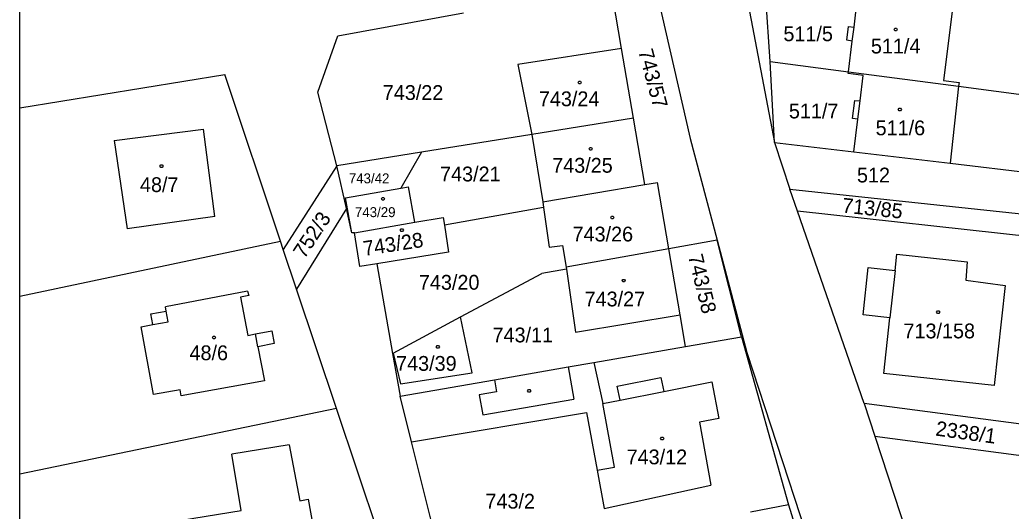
# Model space of a CAD drawing. Extents: x -639590 to -639298, y -1193269 to -1192863.
# Drawn here: x -639590.4 to -639476.5, y -1193051.8 to -1192995.4 of the extents above; entities that cross this region are included whole.
import ezdxf

# ---------------------------------------------------------------- set-up
doc = ezdxf.new("R2010")
doc.units = 0
for name, color, linetype in [('Vrstva 1', 7, 'Continuous'), ('Vrstva 2', 7, 'Continuous'), ('Vrstva 4', 7, 'Continuous'), ('Vrstva 5', 7, 'Continuous'), ('Vrstva 61', 7, 'Continuous')]:
    doc.layers.add(name, color=color, linetype=linetype)

msp = doc.modelspace()

# ---------------------------------------------------------------- linework, layer by layer
at = {"layer": 'Vrstva 1'}
for p, q in [((-639518.33, -1192987.4), (-639513.38, -1193008.98)), ((-639507.5, -1192989.45), (-639503.7, -1193009.43)), ((-639521.26, -1192998.64), (-639522.49, -1192991.48)), ((-639504.21, -1193000.14), (-639504.82, -1192990.96)), ((-639494.57, -1192996.2), (-639494.14, -1192992.64)), ((-639483.21, -1192993.78), (-639484.31, -1193002.34)), ((-639553.86, -1192997.18), (-639539.42, -1192994.56)), ((-639495.4, -1192997.71), (-639495.21, -1192996.13)), ((-639495.21, -1192996.13), (-639494.57, -1192996.2)), ((-639556.15, -1193003.67), (-639553.86, -1192997.18)), ((-639494.77, -1192997.79), (-639495.4, -1192997.71)), ((-639495.21, -1193001.32), (-639494.77, -1192997.79)), ((-639521.26, -1192998.64), (-639533.19, -1193000.49)), ((-639519.89, -1193006.67), (-639521.26, -1192998.64)), ((-639533.19, -1193000.49), (-639531.56, -1193008.54)), ((-639503.7, -1193009.43), (-639504.21, -1193000.14)), ((-639504.21, -1193000.14), (-639495.21, -1193001.32)), ((-639590.39, -1193005.46), (-639566.86, -1193001.65)), ((-639560.45, -1193020.79), (-639566.86, -1193001.65)), ((-639495.23, -1193001.51), (-639495.21, -1193001.32)), ((-639493.52, -1193001.76), (-639495.23, -1193001.51)), ((-639495.21, -1193001.32), (-639482.56, -1193002.99)), ((-639493.88, -1193004.68), (-639493.52, -1193001.76)), ((-639484.31, -1193002.34), (-639482.51, -1193002.57)), ((-639482.56, -1193002.99), (-639483.54, -1193011.82)), ((-639482.51, -1193002.57), (-639482.56, -1193002.99)), ((-639482.56, -1193002.99), (-639459.99, -1193005.96)), ((-639553.99, -1193012.12), (-639556.15, -1193003.67)), ((-639494.73, -1193006.69), (-639494.47, -1193004.61)), ((-639494.47, -1193004.61), (-639493.88, -1193004.68)), ((-639519.89, -1193006.67), (-639531.56, -1193008.54)), ((-639518.6, -1193014.29), (-639519.89, -1193006.67)), ((-639494.13, -1193006.76), (-639494.73, -1193006.69)), ((-639494.58, -1193010.51), (-639494.13, -1193006.76)), ((-639579.55, -1193009.22), (-639569.3, -1193007.9)), ((-639568, -1193017.94), (-639569.3, -1193007.9)), ((-639531.56, -1193008.54), (-639544.27, -1193010.57)), ((-639531.56, -1193008.54), (-639530.31, -1193016.28)), ((-639579.55, -1193009.22), (-639578.08, -1193019.37)), ((-639513.38, -1193008.98), (-639510.28, -1193020.67)), ((-639503.7, -1193009.43), (-639501.94, -1193014.81)), ((-639503.7, -1193009.43), (-639494.58, -1193010.51)), ((-639544.27, -1193010.57), (-639553.99, -1193012.12)), ((-639544.27, -1193010.57), (-639546.64, -1193014.7)), ((-639494.58, -1193010.51), (-639483.54, -1193011.82)), ((-639553.99, -1193012.12), (-639560.14, -1193021.73)), ((-639552.87, -1193017.05), (-639553.99, -1193012.12)), ((-639483.54, -1193011.82), (-639459.46, -1193014.67)), ((-639530.31, -1193016.28), (-639518.6, -1193014.29)), ((-639518.6, -1193014.29), (-639517.16, -1193014.04)), ((-639515.83, -1193021.66), (-639517.16, -1193014.04)), ((-639552.97, -1193015.81), (-639546.64, -1193014.7)), ((-639546.64, -1193014.7), (-639545.76, -1193014.55)), ((-639545.02, -1193018.62), (-639545.76, -1193014.55)), ((-639501.94, -1193014.81), (-639408.9, -1193024.71)), ((-639501.06, -1193017.35), (-639501.94, -1193014.81)), ((-639552.24, -1193019.83), (-639552.97, -1193015.81)), ((-639530.31, -1193016.28), (-639530.22, -1193016.93)), ((-639552.87, -1193017.05), (-639558.61, -1193026.29)), ((-639552.24, -1193019.83), (-639552.87, -1193017.05)), ((-639530.22, -1193016.93), (-639541.62, -1193018.94)), ((-639530.22, -1193016.93), (-639529.57, -1193021.47)), ((-639493.42, -1193039.43), (-639501.06, -1193017.35)), ((-639465.69, -1193021.25), (-639501.06, -1193017.35)), ((-639568, -1193017.94), (-639578.08, -1193019.37)), ((-639551.96, -1193019.82), (-639545.02, -1193018.62)), ((-639545.02, -1193018.62), (-639541.75, -1193018.05)), ((-639541.75, -1193018.05), (-639541.62, -1193018.94)), ((-639541.62, -1193018.94), (-639541.16, -1193022.03)), ((-639551.96, -1193019.82), (-639552.24, -1193019.83)), ((-639551.34, -1193023.7), (-639551.96, -1193019.82)), ((-639590.39, -1193027.1), (-639560.45, -1193020.79)), ((-639560.14, -1193021.73), (-639560.45, -1193020.79)), ((-639529.57, -1193021.47), (-639528.05, -1193021.28)), ((-639528.05, -1193021.28), (-639527.62, -1193023.76)), ((-639510.28, -1193020.67), (-639515.83, -1193021.66)), ((-639507.5, -1193031.78), (-639510.28, -1193020.67)), ((-639510.28, -1193020.67), (-639506.87, -1193033.57)), ((-639558.61, -1193026.29), (-639560.14, -1193021.73)), ((-639541.16, -1193022.03), (-639549.38, -1193023.38)), ((-639515.83, -1193021.66), (-639527.62, -1193023.76)), ((-639514.54, -1193029.25), (-639515.83, -1193021.66)), ((-639489.86, -1193024.14), (-639489.66, -1193022.27)), ((-639489.66, -1193022.27), (-639481.57, -1193023.17)), ((-639549.38, -1193023.38), (-639551.34, -1193023.7)), ((-639549.38, -1193023.38), (-639547.58, -1193033.68)), ((-639481.57, -1193023.17), (-639481.74, -1193025.25)), ((-639539.76, -1193029.49), (-639530.44, -1193024.49)), ((-639527.59, -1193024.01), (-639530.44, -1193024.49)), ((-639527.62, -1193023.76), (-639527.59, -1193024.01)), ((-639527.59, -1193024.01), (-639526.56, -1193031.23)), ((-639493.53, -1193029.25), (-639492.95, -1193023.81)), ((-639492.95, -1193023.81), (-639489.86, -1193024.14)), ((-639481.74, -1193025.25), (-639477.2, -1193025.86)), ((-639564.24, -1193026.51), (-639573.66, -1193028.32)), ((-639564.24, -1193026.51), (-639564.09, -1193027.02)), ((-639554.02, -1193040.01), (-639558.61, -1193026.29)), ((-639477.2, -1193025.86), (-639478.47, -1193037.37)), ((-639564.09, -1193027.02), (-639565.06, -1193027.2)), ((-639565.06, -1193027.2), (-639564.21, -1193031.61)), ((-639575.35, -1193029.14), (-639573.57, -1193028.81)), ((-639575.13, -1193030.37), (-639575.35, -1193029.14)), ((-639573.57, -1193028.81), (-639573.66, -1193028.32)), ((-639526.56, -1193031.23), (-639514.54, -1193029.25)), ((-639513.92, -1193032.9), (-639514.54, -1193029.25)), ((-639490.45, -1193029.58), (-639493.53, -1193029.25)), ((-639576.45, -1193030.61), (-639575.13, -1193030.37)), ((-639547.5, -1193033.64), (-639539.76, -1193029.49)), ((-639538.45, -1193035.9), (-639539.76, -1193029.49)), ((-639491.13, -1193035.97), (-639490.45, -1193029.58)), ((-639575.05, -1193038.4), (-639576.45, -1193030.61)), ((-639564.21, -1193031.61), (-639563.32, -1193031.44)), ((-639563.32, -1193031.44), (-639561.44, -1193031.08)), ((-639561.44, -1193031.08), (-639561.16, -1193032.56)), ((-639561.16, -1193032.56), (-639563.04, -1193032.92)), ((-639513.92, -1193032.9), (-639507.5, -1193031.78)), ((-639507.5, -1193031.78), (-639502.09, -1193051.09)), ((-639563.04, -1193032.92), (-639562.28, -1193036.82)), ((-639547.58, -1193033.68), (-639547.5, -1193033.64)), ((-639547.58, -1193033.68), (-639546.72, -1193038.6)), ((-639547.5, -1193033.64), (-639546.65, -1193037.16)), ((-639524.47, -1193034.73), (-639513.92, -1193032.9)), ((-639506.87, -1193033.57), (-639486.01, -1193097.33)), ((-639527.4, -1193035.24), (-639524.47, -1193034.73)), ((-639524.47, -1193034.73), (-639523.42, -1193039.45)), ((-639546.65, -1193037.16), (-639538.45, -1193035.9)), ((-639535.86, -1193036.71), (-639527.4, -1193035.24)), ((-639478.47, -1193037.37), (-639491.13, -1193035.97)), ((-639562.28, -1193036.82), (-639571.85, -1193038.54)), ((-639546.72, -1193038.6), (-639535.86, -1193036.71)), ((-639521.77, -1193037.44), (-639516.75, -1193036.43)), ((-639516.75, -1193036.43), (-639516.42, -1193038.04)), ((-639516.42, -1193038.04), (-639510.92, -1193036.93)), ((-639510.92, -1193036.93), (-639510.1, -1193041.14)), ((-639571.98, -1193037.85), (-639575.05, -1193038.4)), ((-639571.85, -1193038.54), (-639571.98, -1193037.85)), ((-639521.44, -1193039.05), (-639521.77, -1193037.44)), ((-639545.4, -1193043.83), (-639546.72, -1193038.6)), ((-639523.42, -1193039.45), (-639521.44, -1193039.05)), ((-639468.21, -1193042.77), (-639493.42, -1193039.43)), ((-639493.42, -1193039.43), (-639492.18, -1193043.2)), ((-639554.02, -1193040.01), (-639590.39, -1193047.55)), ((-639547.47, -1193059.58), (-639554.02, -1193040.01)), ((-639545.4, -1193043.83), (-639525.28, -1193040.46)), ((-639525.28, -1193040.46), (-639524.07, -1193047.11)), ((-639510.1, -1193041.14), (-639512.32, -1193041.56)), ((-639512.32, -1193041.56), (-639511.02, -1193048.83)), ((-639541.72, -1193058.45), (-639545.4, -1193043.83)), ((-639492.18, -1193043.2), (-639468.63, -1193046.32)), ((-639492.18, -1193043.2), (-639479.86, -1193080.55)), ((-639559.45, -1193044.19), (-639566.02, -1193045.25)), ((-639559.45, -1193044.19), (-639558.24, -1193050.62)), ((-639564.97, -1193051.71), (-639566.02, -1193045.25)), ((-639524.07, -1193047.11), (-639523.28, -1193051.49)), ((-639523.28, -1193051.49), (-639511.02, -1193048.83)), ((-639558.24, -1193050.62), (-639557.26, -1193050.41)), ((-639557.26, -1193050.41), (-639556.66, -1193053.85)), ((-639571.83, -1193052.82), (-639564.97, -1193051.71)), ((-639502.09, -1193051.09), (-639506.48, -1193051.9)), ((-639502.09, -1193051.09), (-639495.98, -1193070.66))]:
    msp.add_line(p, q, dxfattribs=at)
at = {"layer": 'Vrstva 4'}
for p, q in [((-639494.77, -1192997.79), (-639494.57, -1192996.2)), ((-639494.13, -1193006.76), (-639493.88, -1193004.68)), ((-639489.86, -1193024.14), (-639490.45, -1193029.58)), ((-639573.35, -1193030.05), (-639573.57, -1193028.81)), ((-639575.13, -1193030.37), (-639573.35, -1193030.05)), ((-639563.04, -1193032.92), (-639563.32, -1193031.44)), ((-639527.4, -1193035.24), (-639526.76, -1193038.93)), ((-639535.86, -1193036.71), (-639535.62, -1193038.09)), ((-639535.62, -1193038.09), (-639537.62, -1193038.44)), ((-639521.44, -1193039.05), (-639516.42, -1193038.04)), ((-639537.62, -1193038.44), (-639537.22, -1193040.75)), ((-639537.22, -1193040.75), (-639526.76, -1193038.93)), ((-639522.1, -1193046.75), (-639523.42, -1193039.45)), ((-639524.07, -1193047.11), (-639522.1, -1193046.75))]:
    msp.add_line(p, q, dxfattribs=at)
at = {"layer": 'Vrstva 5'}
for points in [[(-639489.69, -1192996.32), (-639489.6, -1192996.47), (-639489.69, -1192996.62), (-639489.87, -1192996.62), (-639489.96, -1192996.47), (-639489.87, -1192996.32)], [(-639526, -1193002.41), (-639525.91, -1193002.56), (-639526, -1193002.71), (-639526.18, -1193002.71), (-639526.27, -1193002.56), (-639526.18, -1193002.41)], [(-639489.22, -1193005.52), (-639489.13, -1193005.67), (-639489.22, -1193005.82), (-639489.4, -1193005.82), (-639489.49, -1193005.67), (-639489.4, -1193005.52)], [(-639524.73, -1193010.04), (-639524.64, -1193010.19), (-639524.73, -1193010.34), (-639524.91, -1193010.34), (-639525, -1193010.19), (-639524.91, -1193010.04)], [(-639574.03, -1193012.01), (-639573.94, -1193012.16), (-639574.03, -1193012.31), (-639574.21, -1193012.31), (-639574.3, -1193012.16), (-639574.21, -1193012.01)], [(-639548.59, -1193015.77), (-639548.5, -1193015.92), (-639548.59, -1193016.07), (-639548.77, -1193016.07), (-639548.86, -1193015.92), (-639548.77, -1193015.77)], [(-639522.25, -1193017.92), (-639522.16, -1193018.07), (-639522.25, -1193018.22), (-639522.43, -1193018.22), (-639522.52, -1193018.07), (-639522.43, -1193017.92)], [(-639546.42, -1193019.38), (-639546.33, -1193019.53), (-639546.42, -1193019.68), (-639546.6, -1193019.68), (-639546.69, -1193019.53), (-639546.6, -1193019.38)], [(-639520.94, -1193025.17), (-639520.85, -1193025.32), (-639520.94, -1193025.47), (-639521.12, -1193025.47), (-639521.21, -1193025.32), (-639521.12, -1193025.17)], [(-639484.81, -1193028.78), (-639484.72, -1193028.93), (-639484.81, -1193029.08), (-639484.99, -1193029.08), (-639485.08, -1193028.93), (-639484.99, -1193028.78)], [(-639568, -1193031.7), (-639567.91, -1193031.85), (-639568, -1193032), (-639568.18, -1193032), (-639568.27, -1193031.85), (-639568.18, -1193031.7)], [(-639542.29, -1193032.79), (-639542.2, -1193032.94), (-639542.29, -1193033.09), (-639542.47, -1193033.09), (-639542.56, -1193032.94), (-639542.47, -1193032.79)], [(-639531.8, -1193037.83), (-639531.71, -1193037.98), (-639531.8, -1193038.13), (-639531.98, -1193038.13), (-639532.07, -1193037.98), (-639531.98, -1193037.83)], [(-639516.51, -1193043.29), (-639516.42, -1193043.44), (-639516.51, -1193043.59), (-639516.69, -1193043.59), (-639516.78, -1193043.44), (-639516.69, -1193043.29)]]:
    msp.add_lwpolyline(points, close=True, dxfattribs=at)
at = {"layer": 'Vrstva 61'}
msp.add_lwpolyline([(-639590.39, -1193268.77), (-639590.39, -1192863.27)], dxfattribs=at)

# ---------------------------------------------------------------- texts
at = {"layer": 'Vrstva 2'}
for s, height, p in [('511/5', 1.7, (-639502.68, -1192997.81)), ('511/4', 1.7, (-639492.63, -1192999.22)), ('743/22', 1.7, (-639548.7, -1193004.56)), ('743/24', 1.7, (-639530.77, -1193005.28)), ('511/7', 1.7, (-639502.05, -1193006.68)), ('511/6', 1.7, (-639492.09, -1193008.62)), ('743/21', 1.7, (-639542.12, -1193013.92)), ('743/25', 1.7, (-639529.24, -1193012.92)), ('743/42', 1.14, (-639552.6, -1193014.14)), ('512', 1.7, (-639494.23, -1193014.04)), ('48/7', 1.7, (-639576.59, -1193015.14)), ('743/29', 1.14, (-639551.9, -1193018.02)), ('743/26', 1.7, (-639526.9, -1193020.82)), ('743/20', 1.7, (-639544.55, -1193026.36)), ('743/27', 1.7, (-639525.52, -1193028.28)), ('713/158', 1.7, (-639488.89, -1193031.95)), ('743/11', 1.7, (-639536.09, -1193032.41)), ('48/6', 1.7, (-639570.9, -1193034.46)), ('743/39', 1.7, (-639547.17, -1193035.68)), ('743/12', 1.7, (-639520.69, -1193046.42)), ('743/2', 1.7, (-639536.91, -1193051.51))]:
    msp.add_text(s, height=height, dxfattribs=at).set_placement(p)
for s, rotation, p in [('743/57', 284.9892, (-639519.37, -1192998.95)), ('713/85', 354.0879, (-639495.99, -1193017.49)), ('752/3', 56.6082, (-639557.7, -1193022.89)), ('743/28', 8.7663, (-639550.82, -1193022.49)), ('743/58', 283.8433, (-639513.65, -1193022.5)), ('2338/1', 352.1399, (-639485.27, -1193043.11))]:
    msp.add_text(s, height=1.7, rotation=rotation, dxfattribs=at).set_placement(p)

doc.saveas('drawing.dxf')
